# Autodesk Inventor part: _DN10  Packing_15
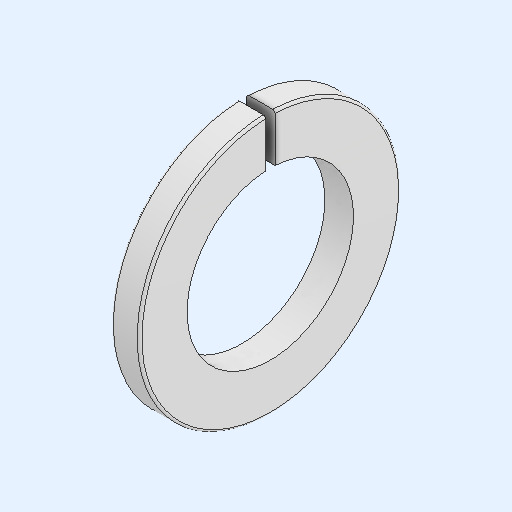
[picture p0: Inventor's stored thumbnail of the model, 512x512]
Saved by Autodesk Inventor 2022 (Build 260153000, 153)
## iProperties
Created: 2021-12
Part Number: _DN10  Packing_15
Material: Generico
Document SubType Name: Modeling
Designer: admin
Density: 1 g/cm^3
Appearance: Default
Author: admin
Revision Number: NONE
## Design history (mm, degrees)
feature "_DN10  Packing"
node "Solido1"
